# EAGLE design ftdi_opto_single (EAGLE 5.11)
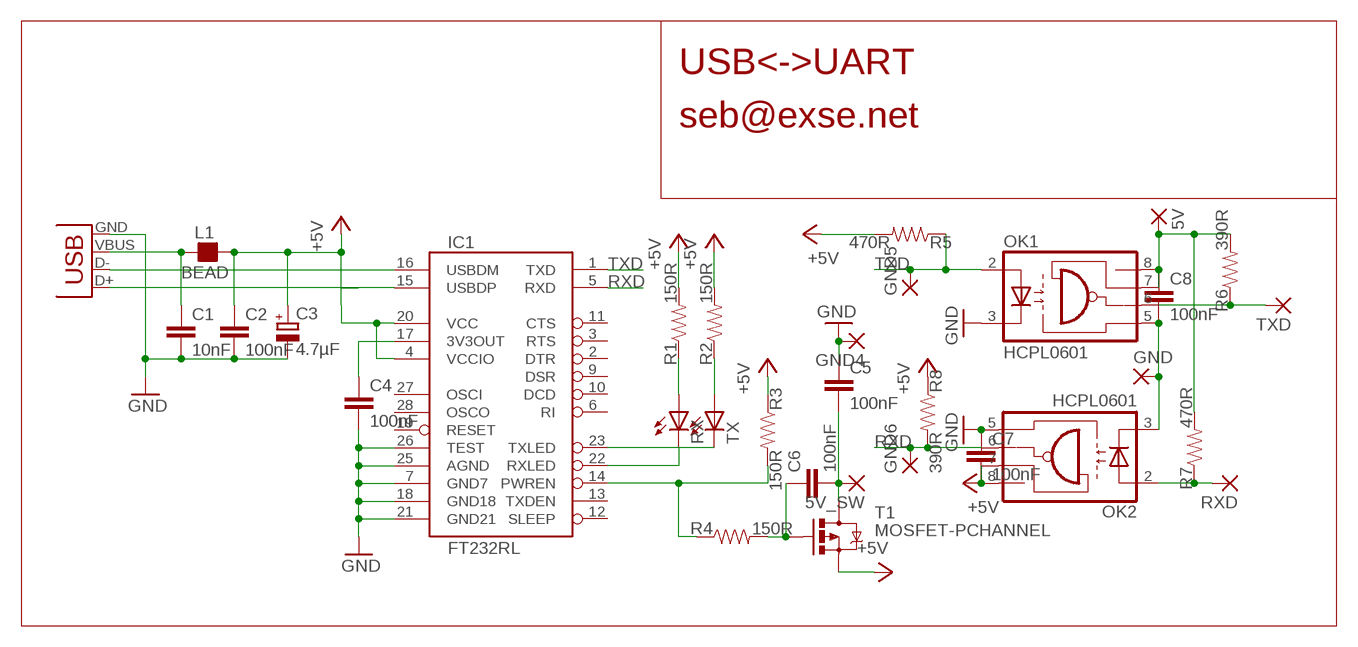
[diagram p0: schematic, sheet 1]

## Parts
5V  SMD2  [SMD1,27-2,54]
5V_SW  SMD2  [SMD1,27-2,54]
C1  10nF  CAP0805  [0805]
C2  100nF  CAP0805  [0805]
C3  4.7µF  CPOL-EUSMCC  [SMC_C]
C4  100nF  CAP0805  [0805]
C5  100nF  CAP0805  [0805]
C6  100nF  CAP0805  [0805]
C7  100nF  CAP0805  [0805]
C8  100nF  CAP0805  [0805]
GND  SMD2  [SMD1,27-2,54]
GND4  SMD2  [SMD1,27-2,54]
GND5  SMD2  [SMD1,27-2,54]
GND6  SMD2  [SMD1,27-2,54]
IC1  FT232RL  FT232RLSSOP  [SSOP28DB]
L1  BEAD  FB_0805  [L0805]
OK1  HCPL0601  [SOIC08]
OK2  HCPL0601  [SOIC08]
R1  150R  RESISTOR  [0805]
R2  150R  RESISTOR  [0805]
R3  150R  RESISTOR  [0805]
R4  150R  RESISTOR  [0805]
R5  470R  RESISTOR  [0805]
R6  390R  RESISTOR  [0805]
R7  470R  RESISTOR  [0805]
R8  390R  RESISTOR  [0805]
RX  LEDCHIP-LED0805  [CHIP-LED0805]
RXD  SMD2  [SMD1,27-2,54]
T1  MOSFET-PCHANNEL  [SOT23]
TX  LEDCHIP-LED0805  [CHIP-LED0805]
TXD  SMD2  [SMD1,27-2,54]
X1  USB-SMD-NS  [USB-MINIB-NOSTOP]

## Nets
5V_SW: 5V_SW.1(P) C5.2 C6.2 T1.3(D)
+5V: C2.1 C3.+ C7.2 IC1.4(VCCIO) IC1.20(VCC) L1.2 OK2.7(VE) OK2.8(VCC) R1.2 R2.2 R3.1 R5.2 R8.1 T1.2(S)
GND: C1.2 C2.2 C3.- C4.2 C5.1 C7.1 GND4.1(P) IC1.7(GND7) IC1.18(GND18) IC1.21(GND21) IC1.25(AGND) IC1.26(TEST) OK1.3(C) OK2.5(GND) X1.GND
N$1: IC1.16(USBDM) X1.D-
N$2: IC1.15(USBDP) X1.D+
N$4: C1.1 L1.1 X1.VBUS
N$5: IC1.14(PWREN) R3.2 R4.1
N$7: C6.1 R4.2 T1.1(G)
N$8: C8.2 GND.1(P) OK1.5(GND) OK2.3(C)
N$9: 5V.1(P) C8.1 OK1.7(VE) OK1.8(VCC) R6.2 R7.2
N$10: OK1.6(VO) R6.1 TXD.1(P)
N$11: OK2.2(A) R7.1 RXD.1(P)
N$19: R1.1 RX.A
N$20: R2.1 TX.A
N$27: IC1.22(RXLED) RX.C
N$28: IC1.23(TXLED) TX.C
N$29: C4.1 IC1.17(3V3OUT)
RXD: GND6.1(P) IC1.5(RXD) OK2.6(VO) R8.2
TXD: GND5.1(P) IC1.1(TXD) OK1.2(A) R5.1
Unconnected: IC1.2(DTR) IC1.3(RTS) IC1.6(RI) IC1.9(DSR) IC1.10(DCD) IC1.11(CTS) IC1.12(SLEEP) IC1.13(TXDEN) IC1.19(RESET) IC1.27(OSCI) IC1.28(OSCO)

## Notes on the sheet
- USB<->UART
- seb@exse.net

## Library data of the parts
5V 5V_SW GND GND4-GND6 RXD TXD = wirepad:SMD2: SMD PAD
C1 C2 C4-C8 = SparkFun:CAP: Capacitor
C3 = resistor:CPOL-EU: POLARIZED CAPACITOR, European symbol
IC1 = SparkFun:FT232RL: USB UART FT232RL 4th Generation USB UART (USB <-> Serial) Controller. Spark Fun Electronics SKU : COM-00650
L1 = rc-master-smd:FB_: FERRITE BEAD
OK1 OK2 = optocoupler:HCPL0601: HEWLETT PACKARD OPTO COUPLER; MF: AGILENT TECHNOLOGIES; MPN: HCPL-0601-000E; OC_FARNELL: 9995102; OC_NEWARK: 88H7776
R1-R8 = SparkFun:RESISTOR: Resistor
RX TX = led:LED: LED
T1 = SparkFun:MOSFET-PCHANNEL
X1 = SparkFun:USB: USB Connectors USB-B-PTH is fully proven SKU : PRT-00139 USB-miniB is fully proven SKU : PRT-00587 USB-A-PCB is untested. USB-A-H is throughly reviewed, but untested. Spark Fun Electronics SKU : PRT-00437 USB-B-SMT is throughly reviewed, but untested. Needs silkscreen touching up. USB-A-S has not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

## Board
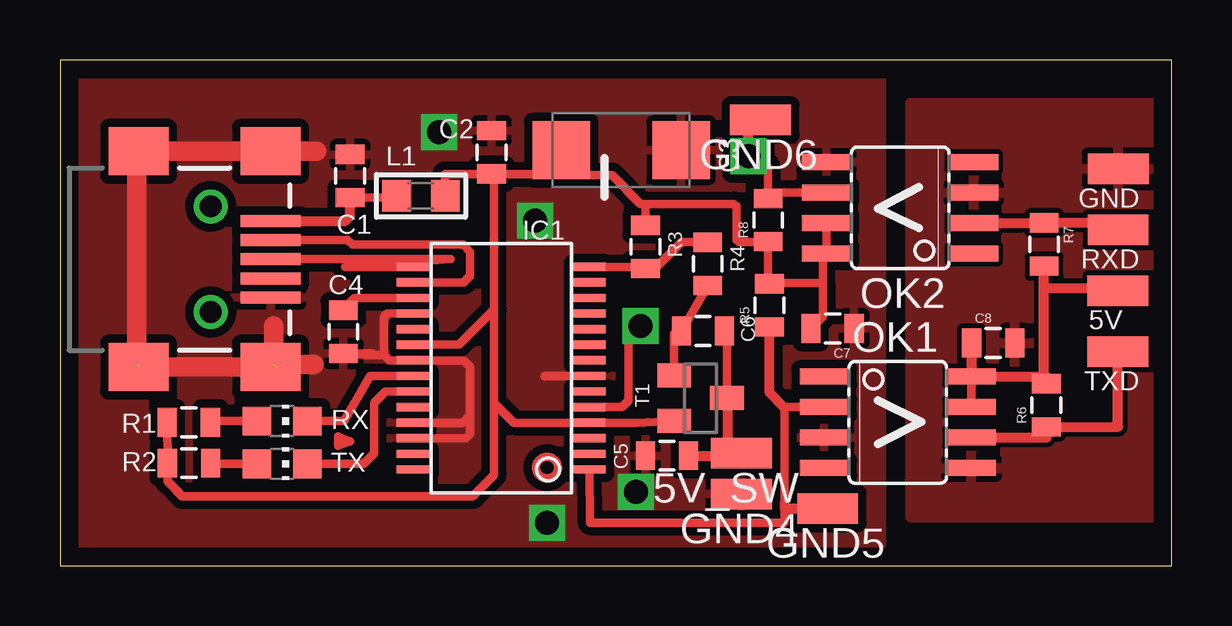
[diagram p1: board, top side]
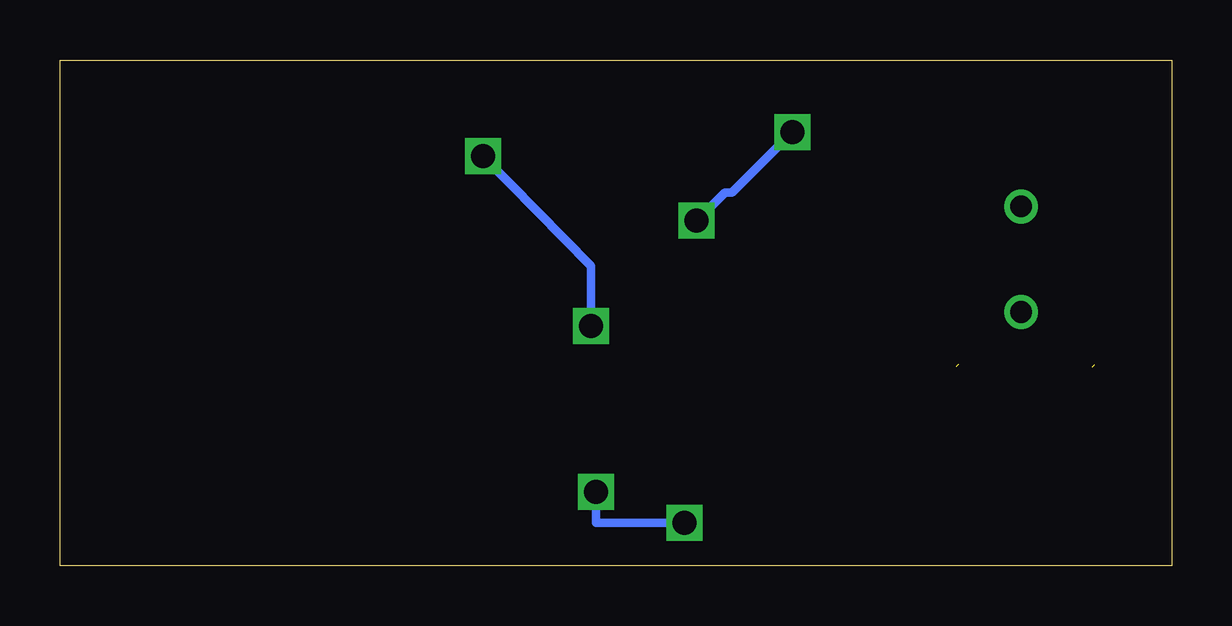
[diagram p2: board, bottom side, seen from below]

Size 46.34 x 21.1 mm. Coordinates in mm from the lower left corner, seen from the top.
Outline: 0,0 46.34,0 46.34,21.1 0,21.1 0,0
Copper layers (1*16): Top 0.035mm / dielectric 1.5mm / Bottom 0.035mm
Design rules "default *": minimum track width 10mil, minimum drill 0.3mm, track to track 8mil, track to pad 8mil, pad to pad 8mil, via to via 8mil, smd to smd 8mil, copper to edge 30mil, drill to drill 8mil, minimum pad ring 10mil, minimum via ring 8mil, stop-mask expansion 4mil, vias tented up to drill 50mil, thermal gap 10mil
tRestrict: 1 lines

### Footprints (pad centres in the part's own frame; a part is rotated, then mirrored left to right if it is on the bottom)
SMD1,27-2,54 = smd 1.27 x 2.54: 1 0,0
0805 = smd 0.8 x 1.2: 1 -0.9,0; 2 0.9,0
SMC_C = smd 2.4 x 2.4: + -2.5,0; - 2.5,0
SSOP28DB = smd 0.348 x 1.397: 1 -4.225,-3.656; 2 -3.575,-3.656; 3 -2.925,-3.656; 4 -2.275,-3.656; 5 -1.625,-3.656; 6 -0.975,-3.656; 7 -0.325,-3.656; 8 0.325,-3.656; 9 0.975,-3.656; 10 1.625,-3.656; 11 2.275,-3.656; 12 2.925,-3.656; 13 3.575,-3.656; 14 4.225,-3.656; 15 4.225,3.656; 16 3.575,3.656; 17 2.925,3.656; 18 2.275,3.656; 19 1.625,3.656; 20 0.975,3.656; 21 0.325,3.656; 22 -0.325,3.656; 23 -0.975,3.656; 24 -1.625,3.656; 25 -2.275,3.656; 26 -2.925,3.656; 27 -3.575,3.656; 28 -4.225,3.656
L0805 = smd 1.2 x 1.3: 1 -1.016,0; 2 1.016,0
SOIC08 = smd 0.66 x 2.032: 1 -1.905,-3.073; 2 -0.635,-3.073; 3 0.635,-3.073; 4 1.905,-3.073; 5 1.905,3.073; 6 0.635,3.073; 7 -0.635,3.073; 8 -1.905,3.073
CHIP-LED0805 = smd 1.2 x 1.2: A 0,-1.05; C 0,1.05
SOT23 = smd 1 x 1.4: 1 -0.95,-1.1; 2 0.95,-1.1; 3 0,1.1
USB-MINIB-NOSTOP = smd 2.5 x 0.5: D+ 2.5,0; D- 2.5,0.8; GND 2.5,-1.6; ID 2.5,-0.8; VBUS 2.5,1.6 | smd 2.5 x 2: G1 -3,-4.5; G2 -3,4.5; G3 2.5,4.5; G4 2.5,-4.5 | drill 0.9 pad 0.8 round: H1 0,2.2 | drill 0.9 pad 0.787 round: H2 0,-2.2

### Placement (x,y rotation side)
5V  44.1,11.48 90 top
5V_SW  28.4,4.7 90 top
C1  12.09,16.26 90 top
C2  17.99,17.25 90 top
C3  23.39,17.34 0 top
C4  11.81,9.76 270 top
C5  25.3,4.6 0 top
C6  26.8,9.8 0 top
C7  32.2,9.9 180 top
C8  38.9,9.3 0 top
GND  44.11,16.56 90 top
GND4  28.4,3 90 top
GND5  32,2.4 90 top
GND6  29.2,18.6 90 top
IC1  18.39,8.25 90 top
L1  15.05,15.43 0 top
OK1  34.92,5.99 270 top
OK2  35.02,14.93 90 top
R1  5.37,5.99 180 top
R2  5.38,4.29 180 top
R3  24.4,13.3 270 top
R4  27,12.6 270 top
R5  29.57,10.87 90 top
R6  41.12,6.7 90 top
R7  41.02,13.41 270 top
R8  29.52,14.42 90 top
RX  9.26,6.04 270 top
RXD  44.1,14.02 90 top
T1  26.7,7 270 top
TX  9.26,4.26 270 top
TXD  44.1,8.94 90 top
X1  6.28,12.79 0 top

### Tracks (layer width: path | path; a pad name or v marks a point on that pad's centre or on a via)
5V_SW
  Top 0.35: T1.3 27.8,9.1 C6.2
  Top 0.406: 27.85,4.35 27.6,4.6 C5.2 | 27.85,4.35 5V_SW.1 | T1.3 27.85,6.95 27.85,4.35
+5V
  Top 0.35: IC1.20 16.62,9.23 18.09,10.69 | R1.2 R2.2 4.48,3.52 5.1,2.9 17.2,2.9 18.1,3.8 | 18.1,3.8 18.09,3.81 | C2.1 16.05,16.35 L1.2 | 18.09,10.69 18.09,16.05 C2.1 | T1.2 24.02,5.98 IC1.4 18.93,5.98 18.1,6.8 | 18.1,6.8 18.1,10.68 18.09,10.69 | 18.1,3.8 18.1,6.8 | 31.8,11.8 31.8,12.88 OK2.8 OK2.7 | 31.8,11.8 29.61,11.8 R5.2 29.52,11.77 R8.1 29.5,13.5 28.3,13.5 28.2,13.6 28.2,15 28.1,15.1 24.4,15.1 | 31.8,11.8 31.8,10.4 C7.2 | C3.+ 20.7,17.15 | C2.1 19.9,16.35 C3.+ | 24.4,15.1 24.2,15.1 23,16.3 21.93,16.3 C3.+ | 24.4,15.1 R3.1
  Top 0.406: L1.2 16.07,15.33
GND  (via drill 1)  (2 unrouted)
  Top 0.35: IC1.26 16.93,5.33 17.1,5.5 17.1,6.3 | 17.1,6.3 17.1,8.3 16.82,8.57 IC1.21 13.72,8.57 13.5,8.8 | IC1.25 16.77,5.98 17.1,6.3 | 13.5,8.8 13.5,10.4 13.62,10.52 IC1.18 | 13.5,8.8 12.67,8.8 C4.2 13.04,8.86 | 25.9,17.9 25.89,17.81 C3.- | IC1.7 20.22,7.92 20.2,7.9
  Top 0.813: 3.3,17.3 10.7,17.3 | 3.2,8.4 3.2,17.5 | 3.3,8.3 9,8.3 | 8.9,10 8.9,8.4 10.6,8.4
  Bottom 0.35: v20.3,1.8 24,1.8 v24,3.1 | v15.8,18.1 18.32,15.57 18.62,15.57 v19.8,14.4
  pour Top (isolate 0.35): 0.1,-0.1 34.26,0 34.26,21.4 0,21.2
N$1
  Top 0.35: IC1.16 16.82,11.82 17.1,12.1 17.1,13.1 16.8,13.4 12.2,13.4 11.99,13.59 X1.D-
N$2
  Top 0.35: X1.D+ 16.29,12.79 11.88,12.47 IC1.15
N$3
  Top 0.35: 11.6,5.4 11.6,5 12.1,5.2 11.6,5.4
N$4
  Top 0.35: C1.1 14.06,15.36 L1.1
  Top 0.406: X1.VBUS 11.89,14.39 12.09,14.59 C1.1 | L1.1 14.03,15.33
N$5
  Top 0.35: IC1.14 24.02,12.47 R3.2 24.8,12.4 25.9,13.5 R4.1
N$7
  Top 0.35: T1.1 25.6,9.7 C6.1 R4.2
N$8
  pour Top: 35.43,2.03 49.55,2.03 49.55,19.3 35.43,19.3
N$9
  Top 0.35: OK1.8 OK1.7
  Top 0.406: 41.02,11.6 41.02,7.6 R6.2 41.12,7.9 OK1.8 | 41.02,11.6 R7.2 | 5V.1 44.1,11.6 41.02,11.6 | OK1.8 C8.1
N$10
  Top 0.406: OK1.6 41.12,5.36 R6.1 44.1,5.8 TXD.1
N$11
  Top 0.406: OK2.2 41.02,14.3 R7.1 44.1,14.31 RXD.1
N$19
  Top 0.35: R1.1 6.42,6.04 RX.A
N$20
  Top 0.35: R2.1 6.41,4.26 TX.A
N$27
  Top 0.35: RX.C 11.84,6.04 12.92,7.92 IC1.22
N$28
  Top 0.35: IC1.23 13.57,7.27 13.1,6.8 13.1,4.7 12.66,4.26 TX.C
N$29
  Top 0.35: C4.1 11.76,10.66 12.27,11.18 IC1.17
RXD  (via drill 1)
  Top 0.35: OK2.6 29.52,15.57 R8.2 29.52,16.62 29.4,16.8 29.1,17.1 v28.7,17.1 | IC1.5 23.43,6.63 23.7,6.9 23.7,10 v24.2,10
  Top 0.406: GND6.1 28.7,18.7 v28.7,17.1
  Bottom 0.35: v24.2,10 24.2,12.5 v28.7,17.1
TXD
  Top 0.35: IC1.1 22.07,4.02 22.1,1.8 30.2,1.8 30.2,2.3 30.2,2.6 30.2,6.6 30.23,6.63 OK1.2 | R5.1 29.6,9.77
  Top 0.406: 30.2,6.6 29.57,7.23 R5.1 | GND5.1 30.2,2.4 30.2,2.6
(copper drawn outside any net)
  shapes: Top circle x1

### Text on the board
bStop: GND | seb@exse.net | RX | TX | 5V | UART <-> USB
